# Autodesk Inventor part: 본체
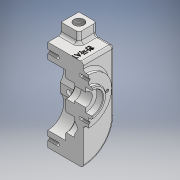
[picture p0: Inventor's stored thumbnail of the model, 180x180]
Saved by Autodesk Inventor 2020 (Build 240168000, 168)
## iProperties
Created: 2024-03
Part Number: 본체
Material: 일반
Document SubType Name: Modeling
Designer: 1강의실14
Density: 1 g/cm^3
Appearance: 기본값
Author: 1강의실14
## Parameters: d1 = 68 mm, d4 = 0, d5 = 33 mm, d6 = 52 mm, d7 = 6 mm, d8 = 0, d9 = 32 mm, d10 = 4 mm, d11 = 0, d18 = 33 mm, d19 = 36 mm, d21 = 12 mm, d23 = 12 mm, d25 = 0, d27 = 0, d31 = 0, d32 = 7 mm, d33 = 60 deg, d34 = 90 deg, d35 = 7.5 mm, d37 = 12.5 mm, d38 = 0.7 mm, d39 = 30 deg, d40 = 90 deg, d41 = 1 mm, d42 = 2 mm, d43 = 45 deg, d44 = 21 mm, d45 = 3.242 mm, d46 = 8 mm, d47 = 4 mm, d48 = 2 mm, d49 = 90 deg, d51 = 118 deg, d53 = 360 deg, d56 = 63.5 mm, d58 = 0, d59 = 26 mm, d60 = 26 mm, d61 = 4.134 mm, d63 = 4 mm, d64 = 2 mm, d65 = 90 deg, d66 = 12 mm, d67 = 118 deg, d68 = 3 mm, d69 = 3 mm, d70 = 4.134 mm, d72 = 4 mm, d73 = 2 mm, d74 = 90 deg, d75 = 12 mm, d76 = 118 deg, d77 = 3 mm, d78 = 3 mm, d79 = 3 mm, d80 = 3 mm, d81 = 3 mm, d82 = 3 mm, d85 = 10.5 mm, d86 = 11 mm, d87 = 0.62479 mm, d88 = 10.589 mm, d89 = 4 mm, d90 = 2 mm, d91 = 90 deg, d92 = 16 mm, d93 = 118 deg, d94 = 28 mm, d95 = 36 mm, d97 = 0, d99 = 63.5 mm, d100 = 8 mm, d101 = 6 mm, d102 = 0, d103 = 0, d105 = 0.5 mm, d106 = 0, d107 = 1 mm, d108 = 2 mm, d109 = 45 deg, d110 = 7.3 mm
